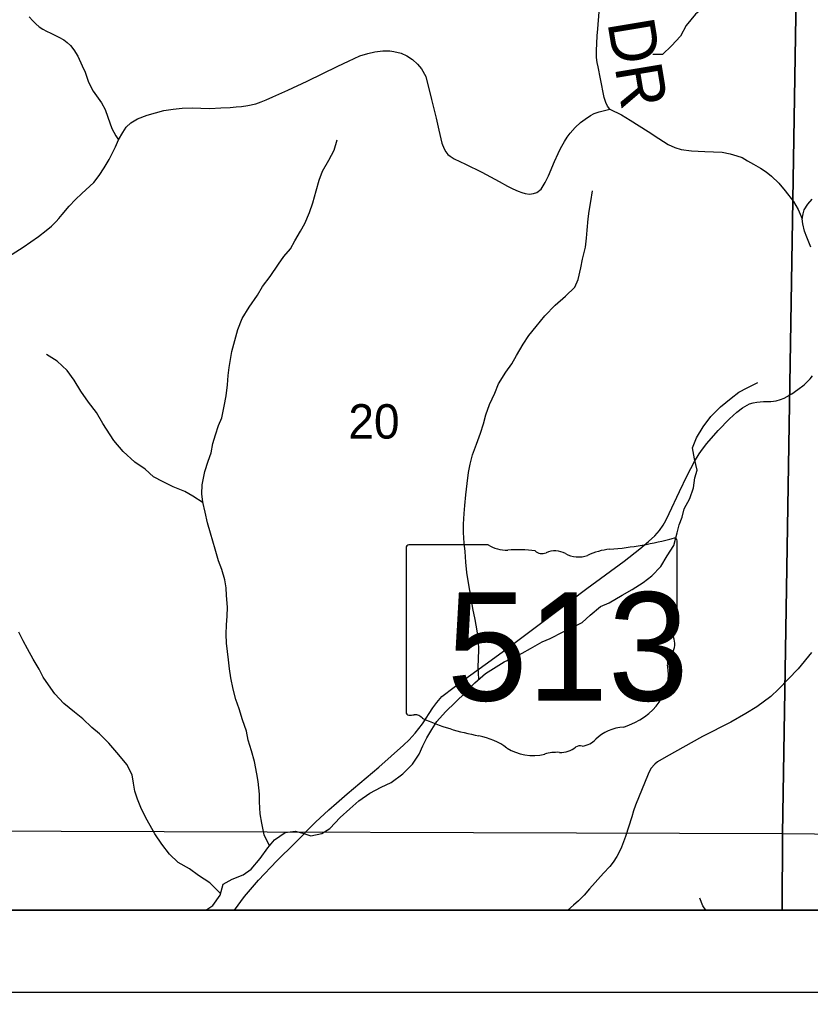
# Model space of a CAD drawing. Extents: x 0 to 34, y -8.9 to 22.
# Drawn here: x 24.724 to 25.687, y 7.004 to 8.187 of the extents above; entities that cross this region are included whole.
import ezdxf

# ---------------------------------------------------------------- set-up
doc = ezdxf.new("R2010")
doc.units = 0
for name, color, linetype in [('GM_X_Corporation', 7, 'Continuous'), ('GM_X_Minor_River', 7, 'Continuous'), ('GM_X_Section_Text', 7, 'Continuous'), ('GM_X_State_Location', 7, 'Continuous'), ('GM_X_State_Route', 7, 'Continuous'), ('GM_X_State_Shield', 7, 'Continuous'), ('GM_X_Township_Road', 7, 'Continuous'), ('GM_X_Township_Road_Text', 7, 'Continuous'), ('SH_Data', 7, 'Continuous')]:
    doc.layers.add(name, color=color, linetype=linetype)

msp = doc.modelspace()

# ---------------------------------------------------------------- linework, layer by layer
at = {"layer": 'GM_X_Corporation'}
for points in [[(23.7167, 11.9654), (23.7167, 7.104), (28.7046, 7.104), (28.7123, 8.2818), (28.7238, 9.1729), (28.7308, 9.4444), (28.7377, 10.2012)], [(24.1844, 10.755), (24.1596, 9.2636), (24.0743, 9.2644), (23.7167, 9.2682), (23.7167, 7.104), (28.7046, 7.104), (28.7123, 8.2818), (28.7238, 9.1729), (28.7308, 9.4444), (28.7377, 10.2012)]]:
    msp.add_lwpolyline(points, dxfattribs=at)
for points in [[(24.6618, 8.2279), (25.6692, 8.2169), (25.6523, 7.1969), (24.6491, 7.2004)], [(25.6692, 8.2169), (26.6846, 8.2041), (26.6684, 7.1864), (25.6523, 7.1969)], [(24.648, 7.104), (25.6521, 7.104), (25.6523, 7.1969), (24.6491, 7.2004)], [(25.6521, 7.104), (26.6681, 7.104), (26.6684, 7.1864), (25.6523, 7.1969)]]:
    msp.add_lwpolyline(points, close=True, dxfattribs=at)
at = {"layer": 'GM_X_Minor_River'}
for points in [[(25.6858, 8.3434), (25.686, 8.3337), (25.6845, 8.3242), (25.6823, 8.312), (25.68, 8.3018), (25.6743, 8.2888), (25.6702, 8.2793), (25.6638, 8.2698), (25.657, 8.2603), (25.6448, 8.2508), (25.6304, 8.2447), (25.613, 8.2374), (25.6001, 8.2298), (25.5902, 8.2248), (25.577, 8.2187), (25.5626, 8.2069), (25.5467, 8.1939), (25.5353, 8.1802), (25.5281, 8.1673), (25.5175, 8.1555), (25.5062, 8.1448), (25.4948, 8.1448)], [(25.0284, 7.1826), (25.0218, 7.1957), (25.0187, 7.2101), (25.0168, 7.2215), (25.016, 7.2359), (25.016, 7.2454), (25.0144, 7.2606), (25.0129, 7.2701), (25.0098, 7.2849), (25.0064, 7.2978), (25.0022, 7.311), (25.0003, 7.3217), (24.9953, 7.3357), (24.9915, 7.349), (24.9873, 7.3603), (24.9842, 7.3729), (24.9811, 7.3869), (24.9796, 7.3979), (24.9784, 7.4085), (24.9761, 7.429), (24.9757, 7.44), (24.9761, 7.4514), (24.9768, 7.4617), (24.9772, 7.4727), (24.976, 7.4867), (24.9756, 7.4962), (24.9737, 7.5061), (24.9702, 7.5186), (24.966, 7.5292), (24.9622, 7.5432), (24.9592, 7.5531), (24.9565, 7.5626), (24.9527, 7.5754), (24.95, 7.5883), (24.9473, 7.6005), (24.9461, 7.6107), (24.9465, 7.6214), (24.9495, 7.6377), (24.9536, 7.6502), (24.9574, 7.6605), (24.9593, 7.6719), (24.9627, 7.6821), (24.9661, 7.6935), (24.9702, 7.7031), (24.9732, 7.7171), (24.9755, 7.7296), (24.9773, 7.7433), (24.9781, 7.7543), (24.9792, 7.7642), (24.9807, 7.7741), (24.9822, 7.7836), (24.9897, 7.8102), (24.995, 7.8238), (25.0033, 7.8375), (25.0135, 7.852), (25.0199, 7.8627), (25.029, 7.8748), (25.0392, 7.8897), (25.0457, 7.8992), (25.0536, 7.9087), (25.0589, 7.9182), (25.0661, 7.93), (25.0714, 7.9395), (25.0767, 7.9528), (25.0808, 7.9646), (25.085, 7.979), (25.0887, 7.992), (25.0929, 8.003), (25.1004, 8.0163), (25.1069, 8.0285), (25.1106, 8.041)], [(25.2829, 7.385), (25.282, 7.3997), (25.2824, 7.4099), (25.2828, 7.4209), (25.2824, 7.4312), (25.2808, 7.4441), (25.2785, 7.4577), (25.2758, 7.471), (25.2739, 7.4816), (25.272, 7.493), (25.2704, 7.5025), (25.2685, 7.5147), (25.267, 7.5276), (25.2662, 7.5405), (25.265, 7.5507), (25.2642, 7.5636), (25.2642, 7.5735), (25.2649, 7.5868), (25.2657, 7.5963), (25.2672, 7.6095), (25.2686, 7.6232), (25.2705, 7.6365), (25.2724, 7.6468), (25.2754, 7.6578), (25.2799, 7.6711), (25.2848, 7.6844), (25.2886, 7.6958), (25.2916, 7.7068), (25.2961, 7.719), (25.3022, 7.733), (25.3067, 7.7444), (25.3158, 7.7585), (25.323, 7.7688), (25.3286, 7.7787), (25.337, 7.7927), (25.3438, 7.803), (25.3528, 7.8141), (25.3631, 7.827), (25.3759, 7.8399), (25.3884, 7.851), (25.3998, 7.8617), (25.4036, 7.8712), (25.407, 7.8856), (25.4092, 7.8959), (25.4126, 7.9107), (25.4141, 7.9213), (25.4148, 7.9312), (25.4159, 7.9448), (25.417, 7.9543), (25.4193, 7.9661), (25.4212, 7.979)], [(24.9474, 7.5997), (24.9351, 7.6077), (24.9252, 7.6133), (24.9112, 7.619), (24.8987, 7.625), (24.8869, 7.6314), (24.877, 7.6405), (24.8645, 7.6492), (24.85, 7.662), (24.839, 7.6756), (24.8253, 7.6961), (24.8176, 7.7094), (24.8081, 7.7222), (24.7986, 7.7355), (24.7906, 7.7487), (24.7822, 7.7605), (24.7697, 7.7718), (24.7568, 7.7801)], [(25.5328, 7.5922), (25.5396, 7.6048), (25.5442, 7.6177), (25.5456, 7.6298), (25.5487, 7.6393), (25.5452, 7.653), (25.5429, 7.6666), (25.5478, 7.6788), (25.5557, 7.6921), (25.5652, 7.7047), (25.5769, 7.7165), (25.5898, 7.7268), (25.5993, 7.734), (25.6095, 7.7394), (25.6224, 7.7459)], [(24.9506, 7.104), (24.9594, 7.1097), (24.9681, 7.1223), (24.9718, 7.1359), (24.9828, 7.1421), (24.9961, 7.147), (25.0059, 7.1539), (25.0169, 7.1672), (25.0264, 7.1802), (25.0343, 7.1897), (25.0472, 7.1985), (25.0594, 7.2004), (25.0688, 7.1978), (25.0787, 7.1948), (25.092, 7.1975), (25.1015, 7.2036), (25.1143, 7.2169), (25.1261, 7.2276), (25.1371, 7.2371), (25.1503, 7.2463), (25.164, 7.2539), (25.1761, 7.2596), (25.1905, 7.2699), (25.2022, 7.2817), (25.2102, 7.2939), (25.2147, 7.3042), (25.2196, 7.3137), (25.2257, 7.324), (25.2317, 7.3335), (25.2423, 7.3456), (25.2544, 7.3571), (25.2666, 7.3689), (25.2779, 7.3807), (25.2912, 7.3921), (25.3006, 7.3982), (25.3139, 7.4062), (25.3234, 7.4108), (25.3355, 7.4166), (25.3457, 7.4223), (25.3598, 7.4307), (25.3696, 7.4345), (25.3855, 7.4429), (25.395, 7.4471), (25.4087, 7.454), (25.4185, 7.4628), (25.431, 7.4734), (25.4416, 7.478), (25.4572, 7.4872), (25.4693, 7.4941), (25.4829, 7.5028), (25.4935, 7.5108), (25.5045, 7.5223), (25.5121, 7.5352), (25.52, 7.5478), (25.5242, 7.563), (25.5268, 7.5728), (25.5302, 7.5823), (25.5328, 7.5922)], [(24.9687, 7.1245), (24.9555, 7.1374), (24.9418, 7.1465), (24.9308, 7.1544), (24.9171, 7.1623), (24.9065, 7.1722), (24.8974, 7.1843), (24.8886, 7.1972), (24.8829, 7.207), (24.8779, 7.2165), (24.8718, 7.229), (24.8676, 7.2392), (24.8642, 7.2491), (24.8627, 7.2586), (24.8611, 7.2688), (24.8546, 7.2813), (24.8451, 7.293), (24.8326, 7.3074), (24.8215, 7.3188), (24.812, 7.3263), (24.801, 7.3369), (24.7911, 7.3448), (24.7778, 7.3554), (24.7672, 7.3675), (24.7592, 7.3781), (24.7527, 7.3876), (24.7478, 7.3971), (24.7405, 7.4096), (24.7337, 7.4221), (24.7287, 7.4316), (24.7234, 7.4422)], [(25.559, 7.104), (25.5555, 7.1095), (25.5517, 7.1189)]]:
    msp.add_lwpolyline(points, dxfattribs=at)
at = {"layer": 'GM_X_State_Route'}
for points in [[(25.687, 7.9107), (25.6822, 7.9226), (25.6793, 7.9298), (25.6771, 7.9389), (25.6765, 7.9449), (25.6774, 7.951), (25.6789, 7.9559), (25.6831, 7.9629), (25.6886, 7.9691)], [(24.9857, 7.104), (24.9977, 7.1208), (25.0147, 7.1405), (25.0373, 7.164), (25.0592, 7.1858), (25.0844, 7.2114), (25.1004, 7.2261), (25.1096, 7.2344), (25.1226, 7.2458), (25.1611, 7.2783), (25.1914, 7.305), (25.198, 7.3112), (25.2055, 7.3193), (25.2144, 7.331), (25.2269, 7.3503), (25.2318, 7.3569), (25.2381, 7.364), (25.2531, 7.3754), (25.2705, 7.3883), (25.2934, 7.4051), (25.3174, 7.4226), (25.3579, 7.4529), (25.4145, 7.4953), (25.4597, 7.5288), (25.4789, 7.5437), (25.4895, 7.5526), (25.497, 7.5595), (25.5026, 7.5661), (25.5071, 7.5725), (25.5103, 7.5781), (25.5147, 7.5866), (25.5272, 7.6134), (25.5366, 7.6327), (25.5454, 7.6497), (25.5511, 7.6591), (25.555, 7.665), (25.5603, 7.6718), (25.5741, 7.6875), (25.5879, 7.7016), (25.5968, 7.7099), (25.6039, 7.7152), (25.6123, 7.7199), (25.6169, 7.7214), (25.6212, 7.7222), (25.6294, 7.7228), (25.638, 7.7229), (25.6445, 7.7237), (25.6498, 7.7251), (25.6543, 7.727), (25.6637, 7.7323), (25.6711, 7.7373), (25.6786, 7.7433), (25.686, 7.7506), (25.6887, 7.7539)]]:
    msp.add_lwpolyline(points, dxfattribs=at)
at = {"layer": 'GM_X_State_Shield'}
for p, q in [((25.5241, 7.4488), (25.5241, 7.5535)), ((25.1946, 7.5451), (25.1946, 7.3449)), ((25.2943, 7.5485), (25.1978, 7.5485)), ((25.5241, 7.4488), (25.5241, 7.4488))]:
    msp.add_line(p, q, dxfattribs=at)
for centre, major_axis, start_param, end_param in [((25.4067, 7.8213), (0.3495, 0), 4.814394, 5.042369), ((25.5205, 7.5539), (0.00367, 0), 6.141152, 7.989035), ((25.1983, 7.5455), (0.00382, 0), 1.712693, 3.28349), ((25.3173, 7.5717), (0.037, 0), 4.042523, 4.731795), ((25.3296, 7.4361), (0.133, 0), 1.404758, 1.657858), ((25.3598, 7.5465), (0.0107, 0), 3.836095, 5.185415), ((25.3755, 7.5234), (0.0222, 0), 0.950623, 2.079405), ((25.4513, 7.4874), (0.0703, 0), 1.699011, 2.107814), ((25.4041, 7.5551), (0.0267, 0), 4.081561, 5.145723), ((25.5233, 7.4411), (0.00568, 0), 1.883978, 3.671073), ((25.5202, 7.4484), (0.00393, 0), 5.05454, 6.418171), ((25.4872, 7.4279), (0.0341, 0), 5.934695, 6.695948), ((25.5373, 7.405), (0.0248, 0), 2.387724, 3.262537), ((25.4263, 7.3916), (0.0874, 0), 5.101752, 6.440018), ((25.1984, 7.3445), (0.00385, 0), 3.00124, 4.508301), ((25.199, 7.365), (0.0294, 0), 4.665946, 4.897461), ((25.205, 7.3334), (0.0106, 0), 0.519207, 1.627899), ((25.3388, 7.5132), (0.2524, 0), 4.195997, 4.488961), ((25.4632, 7.2887), (0.0479, 0), 1.647645, 2.488434), ((25.2635, 7.255), (0.079, 0), 0.823519, 1.323587), ((25.3816, 7.3174), (0.0267, 0), 4.691044, 5.507374), ((25.4057, 7.298), (0.00752, 0), 1.147584, 2.315152), ((25.4025, 7.3255), (0.0282, 0), 4.937069, 5.64225), ((25.349, 7.3324), (0.0501, 0), 4.026481, 4.996735), ((25.3779, 7.2632), (0.0412, 0), 1.495662, 1.94098)]:
    msp.add_ellipse(centre, major_axis=major_axis, ratio=0.8, start_param=start_param, end_param=end_param, dxfattribs=at)
at = {"layer": 'GM_X_Township_Road'}
for points in [[(24.736, 8.1907), (24.7402, 8.1858), (24.7438, 8.182), (24.7481, 8.1784), (24.7523, 8.1756), (24.7569, 8.1733), (24.7622, 8.1706), (24.7672, 8.1684), (24.7721, 8.166), (24.7778, 8.1625), (24.7819, 8.1594), (24.786, 8.156), (24.79, 8.1506), (24.795, 8.1427), (24.8005, 8.1309), (24.8038, 8.1233), (24.808, 8.1111), (24.8136, 8.1002), (24.8237, 8.0859), (24.8281, 8.078), (24.8316, 8.0688), (24.8363, 8.055), (24.8413, 8.0458), (24.8447, 8.041)], [(25.4424, 8.0785), (25.4396, 8.082), (25.4375, 8.0864), (25.4353, 8.0926), (25.4308, 8.1152), (25.4282, 8.1297), (25.4271, 8.1351), (25.4262, 8.1413), (25.4259, 8.1496), (25.4265, 8.1582), (25.4271, 8.1675), (25.4279, 8.176), (25.4293, 8.1968)], [(24.6848, 7.883), (24.7287, 7.9106), (24.7471, 7.9234), (24.7566, 7.9307), (24.7631, 7.9361), (24.7688, 7.9419), (24.7721, 7.9456), (24.7759, 7.9502), (24.7844, 7.9604), (24.7923, 7.9686), (24.7999, 7.9757), (24.8147, 7.9892), (24.8209, 7.9977), (24.8272, 8.007), (24.8332, 8.017), (24.8386, 8.0275), (24.8409, 8.0325), (24.8447, 8.041), (24.8499, 8.05), (24.8537, 8.0563), (24.8595, 8.0619), (24.8676, 8.0668), (24.8794, 8.071), (24.8996, 8.0768), (24.911, 8.0784), (24.9219, 8.0796), (24.9344, 8.0798), (24.9447, 8.0797), (24.9555, 8.0792), (24.9689, 8.0799), (24.9802, 8.0805), (24.9877, 8.0812), (24.9942, 8.0818), (25.0017, 8.0827), (25.0114, 8.085), (25.018, 8.0871), (25.0243, 8.0896), (25.0322, 8.0933), (25.0507, 8.1016), (25.0739, 8.1125), (25.1114, 8.1305), (25.1243, 8.1369), (25.1383, 8.1431), (25.1477, 8.1462), (25.1565, 8.1481), (25.1662, 8.1494), (25.1745, 8.1493), (25.1796, 8.1487), (25.1884, 8.1466), (25.1955, 8.1434), (25.2023, 8.1388), (25.2081, 8.1331), (25.213, 8.1273), (25.2184, 8.1182), (25.2254, 8.0903), (25.2309, 8.0675), (25.2343, 8.0527), (25.238, 8.0372), (25.2408, 8.0303), (25.2427, 8.0266), (25.2453, 8.0234), (25.2482, 8.0211), (25.2531, 8.0181), (25.2667, 8.0116), (25.2864, 8.0018), (25.3076, 7.9904), (25.318, 7.9849), (25.3241, 7.9815), (25.3308, 7.9786), (25.3352, 7.9769), (25.3393, 7.9758), (25.3447, 7.975), (25.3494, 7.9757), (25.3535, 7.9771), (25.3586, 7.981), (25.3638, 7.9893), (25.3676, 7.9971), (25.375, 8.0149), (25.3794, 8.0244), (25.3821, 8.0305), (25.387, 8.0389), (25.3906, 8.0445), (25.3942, 8.049), (25.4003, 8.0561), (25.4067, 8.062), (25.4124, 8.0664), (25.4187, 8.0705), (25.4234, 8.073), (25.4293, 8.0753), (25.4424, 8.0785)], [(25.4424, 8.0785), (25.4567, 8.0713), (25.4672, 8.0651), (25.4891, 8.0514), (25.5018, 8.0426), (25.5132, 8.0354), (25.5212, 8.0319), (25.5291, 8.0292), (25.5416, 8.0276), (25.5579, 8.0269), (25.5788, 8.026), (25.5888, 8.0242), (25.597, 8.0217), (25.6033, 8.0194), (25.6097, 8.0157), (25.6172, 8.0115), (25.6255, 8.0066), (25.6324, 8.0023), (25.639, 7.9969), (25.648, 7.9882), (25.6557, 7.979), (25.6659, 7.966), (25.6716, 7.9565), (25.6765, 7.9449)], [(25.6876, 7.4177), (25.6714, 7.3978), (25.6477, 7.3728), (25.6384, 7.3639), (25.6213, 7.3515), (25.6077, 7.3433), (25.5894, 7.3329), (25.5549, 7.3154), (25.511, 7.2906), (25.5004, 7.2847), (25.4969, 7.2818), (25.4922, 7.2765), (25.4888, 7.2697), (25.4737, 7.2319), (25.4713, 7.2249), (25.469, 7.2178), (25.4614, 7.1936), (25.4564, 7.1809), (25.4538, 7.1746), (25.4507, 7.1695), (25.4464, 7.1627), (25.4424, 7.1573), (25.4345, 7.1492), (25.4174, 7.1302), (25.411, 7.1224), (25.4043, 7.1157), (25.3981, 7.1102), (25.3913, 7.104)]]:
    msp.add_lwpolyline(points, dxfattribs=at)
at = {"layer": 'SH_Data'}
for points in [[(23.6167, 14.004), (30.6167, 14.004), (30.6167, 7.004), (23.6167, 7.004)], [(23.7167, 13.904), (30.5167, 13.904), (30.5167, 7.104), (23.7167, 7.104)]]:
    msp.add_lwpolyline(points, close=True, dxfattribs=at)

# ---------------------------------------------------------------- texts
at = {"layer": 'GM_X_Section_Text'}
msp.add_text('20', height=0.04186, rotation=0, dxfattribs=at).set_placement((25.1242, 7.6777))
at = {"layer": 'GM_X_State_Location'}
for s, p in [('s', (25.3557, 7.4317)), ('r', (25.3556, 7.4317))]:
    msp.add_text(s, height=0.000189, dxfattribs=at).set_placement(p)
msp.add_text('513', height=0.000189, rotation=0, dxfattribs=at).set_placement((25.2888, 7.4179))
at = {"layer": 'GM_X_State_Shield'}
msp.add_text('513', height=0.13184, dxfattribs=at).set_placement((25.244, 7.359))
at = {"layer": 'GM_X_Township_Road_Text'}
msp.add_text('DR', height=0.05682, rotation=279.4626, dxfattribs=at).set_placement((25.4392, 8.1838))

doc.saveas('drawing.dxf')
